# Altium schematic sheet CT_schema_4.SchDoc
size 283 x 174 mm
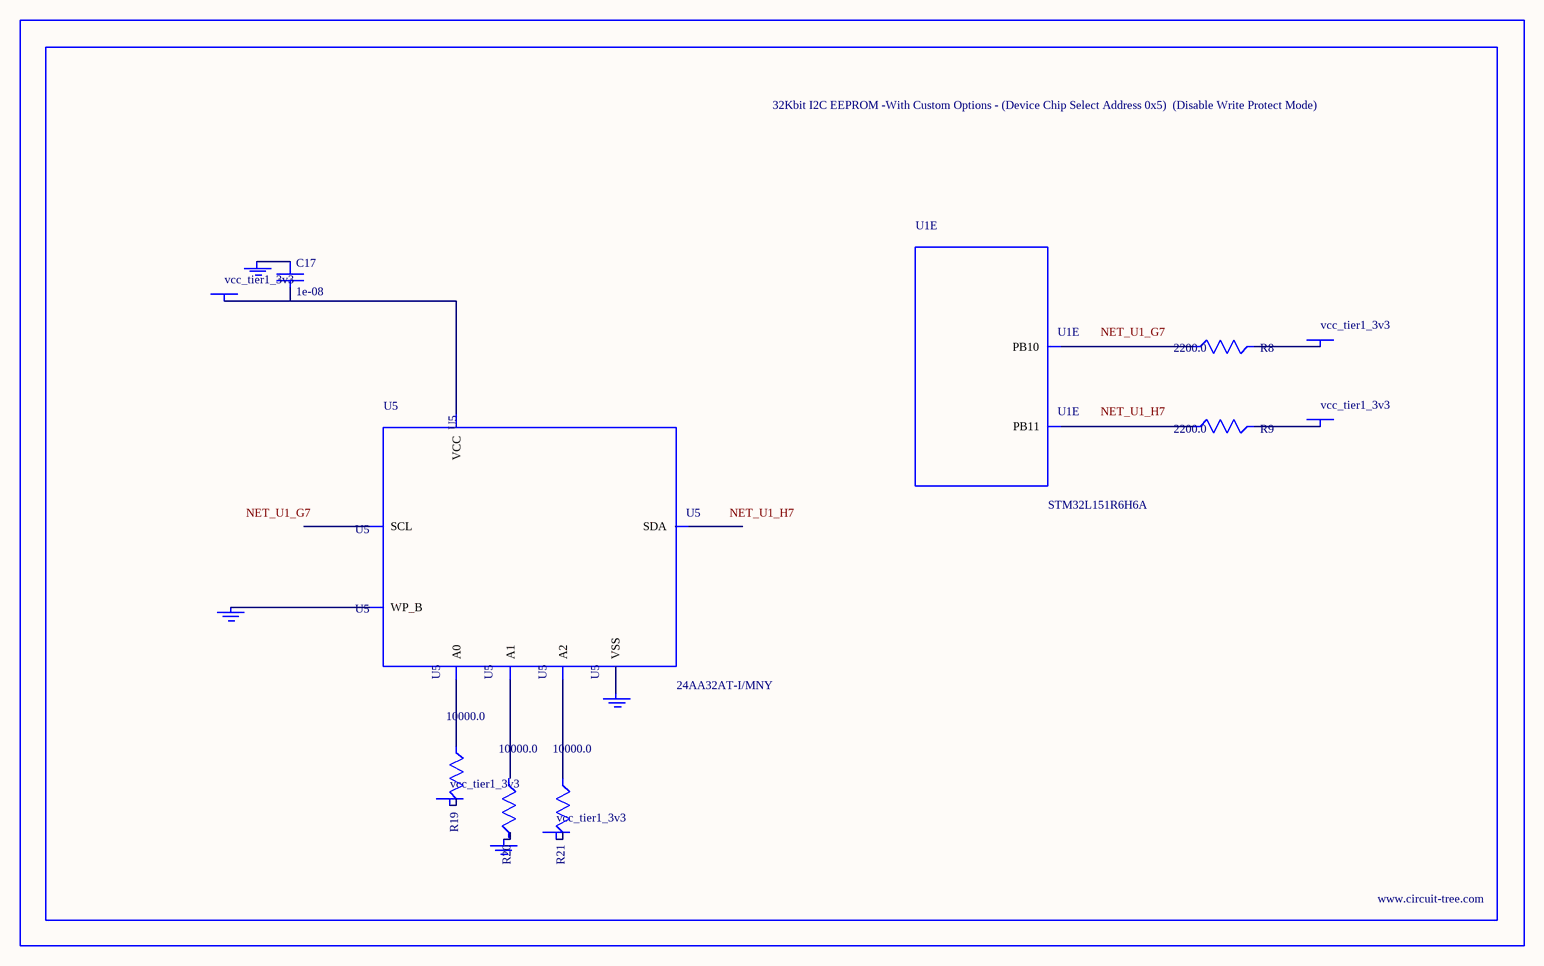
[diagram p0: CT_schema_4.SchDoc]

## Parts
BORDER3  (no value)
C17  1e-08  [C0402]
GND_INSTANCE_3_0  (no value)
GND_INSTANCE_3_1  (no value)
GND_INSTANCE_3_2  (no value)
GND_INSTANCE_3_3  (no value)
POWER_INSTANCE_3_0  vcc_tier1_3v3
POWER_INSTANCE_3_1  vcc_tier1_3v3
POWER_INSTANCE_3_2  vcc_tier1_3v3
POWER_INSTANCE_3_3  vcc_tier1_3v3
POWER_INSTANCE_3_4  vcc_tier1_3v3
R8  2200.0  [R0603]
R9  2200.0  [R0603]
R19  10000.0  [R0603]
R20  10000.0  [R0603]
R21  10000.0  [R0603]
U1  STM32L151R6H6A  [TFBGA64]  (part E of 7)
U5  24AA32AT-I/MNY  [TDFN-8/6MM]

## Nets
NetC17_1: C17.1 GND_INSTANCE_3_2.0(GND)
NetC17_2: C17.2 POWER_INSTANCE_3_2.0(PWR) U5.8(VCC)
NetGND_INSTANCE_3_1_0: GND_INSTANCE_3_1.0(GND) U5.7(WP_B)
NetGND_INSTANCE_3_3_0: GND_INSTANCE_3_3.0(GND) U5.4(VSS)
NetPOWER_INSTANCE_3_0_0: POWER_INSTANCE_3_0.0(PWR) R19.2
NetPOWER_INSTANCE_3_1_0: POWER_INSTANCE_3_1.0(PWR) R21.2
NetPOWER_INSTANCE_3_3_0: POWER_INSTANCE_3_3.0(PWR) R8.2
NetPOWER_INSTANCE_3_4_0: POWER_INSTANCE_3_4.0(PWR) R9.2
NetR8_1: R8.1 U1.G7(PB10)
NetR9_1: R9.1 U1.H7(PB11)
NetR19_1: R19.1 U5.1(A0)
NetR21_1: R21.1 U5.3(A2)

Not connected (* = marked no-connect by the designer): GND_INSTANCE_3_0 0(GND); R20 1 2; U5 2(A1) 5(SDA) 6(SCL)

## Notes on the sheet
- Labels drawn without touching a wire or pin: NET_U1_G7, NET_U1_H7

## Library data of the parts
BORDER3 = BORDER_PAGE3
C17 = C0402C103K3RAC
GND_INSTANCE_3_0-GND_INSTANCE_3_3 = GND
POWER_INSTANCE_3_0-POWER_INSTANCE_3_4 = PWR
R8 R9 = RC0603JR-072K2L
R19-R21 = RC0603JR-0710KL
